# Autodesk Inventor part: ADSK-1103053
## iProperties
Shininess: 50.0
Length Units: 11272
Angle Units: 11279
Time Units: 11290
Mass Units: 11286
Length Display Precision: 4
Angle Display Precision: 2
Compacted: True
Created: 2000-08
Part Number: ADSK-1103053
Document SubType Name: Modeling
Description: TAPER NUT
Mass: 1.42288 g
Surface Area: 3.58073 cm^2
Volume: 0.16799 cm^3
Density: 8.47 g/cm^3
Material: Brass, Soft Yellow
Density: 0.0
Volumn: 0.0
Area: 0.0
PropertySet Name: Model Information
Control State: 0
Master: False
Checked Out: False
Author: Autodesk, Inc.
